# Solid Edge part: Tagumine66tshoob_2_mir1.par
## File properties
Author: KULL
Template: Iso Metric Part.par
Last saved by: KULL
Revision: 2
Application: Solid Edge
Accuracy: 0,990
Username: KULL
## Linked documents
Tagumine66tshoob_2.par
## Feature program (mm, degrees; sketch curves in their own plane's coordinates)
part copy "CopiedPart_1"
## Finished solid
Body 1: solid body, 15 faces, 15 edges, 0 vertices.
  Faces by surface: cylinder 6, plane 6, torus 2, blend 1
  Edges by curve: circle 13, intersection 2
Bounding box of the edges (mm; curved faces can reach further): 20.000 x 45.562 x 11.446, from (-352.46, -85.5617, 50.3651) to (-332.46, -40, 61.811).
Cylindrical faces by radius (mm): R2 x1, R2.5 x1, R2.5057 x1, R3 x2, R5 x1
Toroidal faces (ring radius, tube radius in mm): R4.6 r0.4 x2
Planar faces by outward normal: +x 1, -x 1, oblique 4
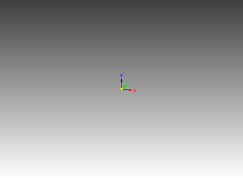
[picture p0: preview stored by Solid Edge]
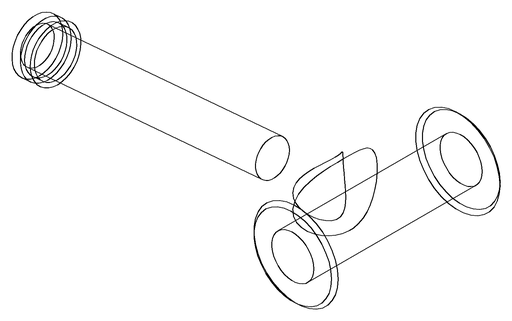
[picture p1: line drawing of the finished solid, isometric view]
